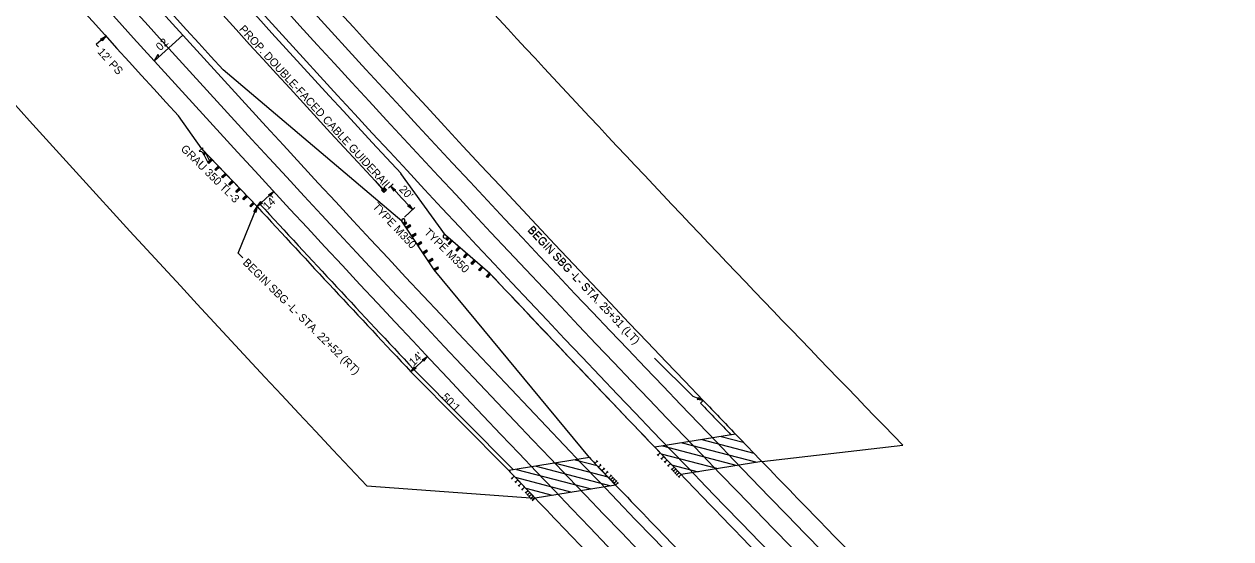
# Model space of a CAD drawing. Extents: x 1602193 to 1605074, y 908180 to 910630.
# Drawn here: x 1602900 to 1603654, y 909219 to 909541 of the extents above; entities that cross this region are included whole.
import ezdxf

# ---------------------------------------------------------------- set-up
doc = ezdxf.new("R2010")
doc.units = 0
for name, color, linetype in [('Prop Approach Slab', 7, 'Continuous'), ('Prop Approach Slab Hatching', 7, 'Continuous'), ('Prop Cable Guiderail Anchor Unit CELL', 7, 'Continuous'), ('Prop Cable Guiderail Double Face', 7, 'Continuous'), ('Prop Conc Shoulder Berm Gutter', 7, 'Continuous'), ('Prop Dimension', 7, 'Continuous'), ('Prop Dimension Text', 7, 'Continuous'), ('Prop DSN Text', 7, 'Continuous'), ('Prop EOT', 7, 'Continuous'), ('Prop Fence Woven Wire', 7, 'Continuous'), ('Prop Guardrail', 7, 'Continuous'), ('Prop Guardrail Anchor Unit CELL', 7, 'Continuous'), ('Prop Lane Lines', 7, 'Continuous'), ('Prop Paved Shoulder', 7, 'Continuous'), ('Prop Roadway Bridge', 7, 'Continuous'), ('Prop Structure Anchor Unit CELL', 7, 'Continuous'), ('Prop Superelevation  Arrow CELL', 7, 'Continuous'), ('Prop Superelevation Label', 7, 'Continuous')]:
    doc.layers.add(name, color=color, linetype=linetype)

msp = doc.modelspace()

# ---------------------------------------------------------------- linework, layer by layer
at = {"layer": 'Prop Approach Slab'}
for p, q in [((1603344.36, 909284.54), (1603293.92, 909276.42)), ((1603253.14, 909269.86), (1603202.83, 909261.76))]:
    msp.add_line(p, q, dxfattribs=at)
for radius, start, end in [(14299.86, 223.910608, 224.005758), (14341.86, 223.794227, 223.888965), (14375.86, 223.700621, 223.795026), (14417.86, 223.585755, 223.679755)]:
    msp.add_arc((1613646.31, 919202), radius, start, end, dxfattribs=at)
at = {"layer": 'Prop Approach Slab Hatching'}
for p, q in [((1603311.07, 909279.18), (1603357.71, 909266.94)), ((1603323.28, 909281.15), (1603355.88, 909272.59)), ((1603335.48, 909283.11), (1603349.21, 909279.51)), ((1603297.87, 909272.31), (1603333.29, 909263.01)), ((1603298.86, 909277.22), (1603345.5, 909264.98)), ((1603207.63, 909262.53), (1603254.28, 909250.29)), ((1603219.84, 909264.5), (1603266.49, 909252.26)), ((1603232.05, 909266.46), (1603264.54, 909257.94)), ((1603244.26, 909268.43), (1603257.94, 909264.84)), ((1603304.5, 909265.4), (1603321.08, 909261.05)), ((1603206.8, 909257.58), (1603242.07, 909248.33)), ((1603213.37, 909250.69), (1603229.86, 909246.36))]:
    msp.add_line(p, q, dxfattribs=at)
at = {"layer": 'Prop Cable Guiderail Anchor Unit CELL'}
for p, q in [((1603108.43, 909454.43), (1603119.29, 909442.68)), ((1603119.29, 909442.68), (1603124.72, 909436.81)), ((1603119.29, 909442.68), (1603124.87, 909436.94)), ((1603119.29, 909442.68), (1603124.56, 909436.68)), ((1603119.29, 909442.68), (1603119.29, 909442.68)), ((1603124.78, 909438.22), (1603123.31, 909436.86)), ((1603124.67, 909435.39), (1603123.31, 909436.86)), ((1603124.86, 909437.27), (1603124.25, 909436.71)), ((1603124.59, 909436.34), (1603124.25, 909436.71)), ((1603125.2, 909436.91), (1603124.59, 909436.34)), ((1603126.14, 909436.75), (1603124.67, 909435.39)), ((1603126.14, 909436.75), (1603124.78, 909438.22)), ((1603125.2, 909436.91), (1603124.86, 909437.27))]:
    msp.add_line(p, q, dxfattribs=at)
at = {"layer": 'Prop Cable Guiderail Double Face'}
msp.add_arc((1613646.31, 919202), 14354.86, 219.580763, 222.768936, dxfattribs=at)
at = {"layer": 'Prop Conc Shoulder Berm Gutter'}
msp.add_line((1603141.65, 909323.51), (1603202.83, 909261.76), dxfattribs=at)
for radius, start, end in [(14419.86, 222.680346, 223.240451), (14299.86, 223.794464, 223.910608)]:
    msp.add_arc((1613646.31, 919202), radius, start, end, dxfattribs=at)
at = {"layer": 'Prop Dimension'}
for p, q in [((1603055.88, 909436.16), (1603045.59, 909426.67)), ((1603130.45, 909440.76), (1603127.6, 909438.11)), ((1603144.1, 909426.16), (1603137.63, 909420.14)), ((1603151.85, 909333.1), (1603141.65, 909323.51))]:
    msp.add_line(p, q, dxfattribs=at)
msp.add_arc((1613646.31, 919202), 14349.94, 222.868721, 222.948526, dxfattribs=at)
at = {"layer": 'Prop Dimension Text'}
for p, q in [((1602951.05, 909533.17), (1602945.12, 909527.8)), ((1602945.12, 909527.8), (1602946.47, 909526.32))]:
    msp.add_line(p, q, dxfattribs=at)
at = {"layer": 'Prop DSN Text'}
for p, q in [((1603033.65, 909397.62), (1603045.59, 909426.67)), ((1603033.65, 909397.62), (1603036.7, 909394.6)), ((1603317.98, 909308), (1603293.74, 909331.98)), ((1603324.28, 909305.45), (1603317.98, 909308))]:
    msp.add_line(p, q, dxfattribs=at)
for points in [[(1602947.79, 909531.11), (1602951.05, 909533.17), (1602948.68, 909530.12), (1602948.58, 909530.93)], [(1603052.63, 909434.07), (1603055.88, 909436.16), (1603053.54, 909433.09), (1603053.43, 909433.9)], [(1603131.12, 909436.2), (1603129.03, 909439.44), (1603132.1, 909437.1), (1603131.3, 909436.99)], [(1603048.83, 909428.76), (1603045.59, 909426.67), (1603047.93, 909429.74), (1603048.04, 909428.93)], [(1603043.52, 909423.41), (1603045.59, 909426.67), (1603044.76, 909422.9), (1603044.32, 909423.58)], [(1603140.53, 909428.03), (1603142.63, 909424.8), (1603139.56, 909427.12), (1603140.36, 909427.24)], [(1603148.62, 909330.98), (1603151.85, 909333.1), (1603149.54, 909330.01), (1603149.42, 909330.81)], [(1603144.88, 909325.63), (1603141.65, 909323.51), (1603143.96, 909326.6), (1603144.08, 909325.79)], [(1603321, 909307.49), (1603324.28, 909305.45), (1603320.5, 909306.25), (1603321.19, 909306.7)]]:
    msp.add_lwpolyline(points, close=True, dxfattribs=at)
at = {"layer": 'Prop EOT'}
for radius, start, end in [(14311.86, 219.480877, 227.661141), (14335.86, 219.480979, 227.66104), (14381.86, 219.480979, 227.66104), (14405.86, 219.479716, 227.662303)]:
    msp.add_arc((1613646.31, 919202), radius, start, end, dxfattribs=at)
at = {"layer": 'Prop Fence Woven Wire'}
for p, q in [((1603360.85, 909267.45), (1603448.88, 909277.66)), ((1603114.19, 909252.19), (1603219.15, 909244.64))]:
    msp.add_line(p, q, dxfattribs=at)
for centre, radius, start, end in [((1613600.64, 919155.95), 14423.95, 219.415042, 223.36309), ((1613597.21, 919158.4), 14163.95, 222.076817, 224.234567)]:
    msp.add_arc(centre, radius, start, end, dxfattribs=at)
at = {"layer": 'Prop Guardrail'}
for p, q in [((1603253.14, 909269.86), (1603156.2, 909387.08)), ((1603141.65, 909323.51), (1603202.83, 909261.76))]:
    msp.add_line(p, q, dxfattribs=at)
for radius, start, end in [(14419.86, 222.680346, 223.240451), (14341.86, 223.196842, 223.814059), (14375.86, 223.700621, 223.720297), (14417.86, 223.585755, 223.605244)]:
    msp.add_arc((1613646.31, 919202), radius, start, end, dxfattribs=at)
at = {"layer": 'Prop Guardrail Anchor Unit CELL'}
for p, q in [((1603011.57, 909463.31), (1603009.42, 909461.32)), ((1603009.42, 909461.32), (1603010.84, 909461.03)), ((1603010.84, 909461.03), (1603012.24, 909459.53)), ((1603011.74, 909461.87), (1603011.57, 909463.31)), ((1603013.13, 909460.36), (1603011.74, 909461.87)), ((1603012.86, 909460.75), (1603011.78, 909459.71)), ((1603011.78, 909459.71), (1603013.55, 909460.03)), ((1603012.47, 909458.99), (1603011.78, 909459.71)), ((1603012.47, 909458.99), (1603012.13, 909459.35)), ((1603012.24, 909459.53), (1603012.68, 909459.95)), ((1603012.86, 909460.75), (1603012.47, 909458.99)), ((1603013.55, 909460.03), (1603012.47, 909458.99)), ((1603014.74, 909454.38), (1603012.47, 909458.99)), ((1603012.68, 909459.95), (1603013.13, 909460.36)), ((1603045.59, 909426.67), (1603013.21, 909460.39)), ((1603015.84, 909455.44), (1603013.55, 909460.03)), ((1603016.95, 909456.5), (1603014.74, 909454.38)), ((1603014.74, 909454.38), (1603016.54, 909454.71)), ((1603015.43, 909453.65), (1603014.74, 909454.38)), ((1603017.64, 909455.78), (1603015.43, 909453.65)), ((1603015.84, 909455.44), (1603015.43, 909453.65)), ((1603017.64, 909455.78), (1603015.84, 909455.44)), ((1603016.54, 909454.71), (1603015.84, 909455.44)), ((1603016.54, 909454.71), (1603016.95, 909456.5)), ((1603021.31, 909451.95), (1603019.15, 909449.87)), ((1603022.01, 909451.23), (1603019.84, 909449.15)), ((1603020.23, 909450.91), (1603019.84, 909449.15)), ((1603022.01, 909451.23), (1603020.23, 909450.91)), ((1603020.92, 909450.19), (1603020.23, 909450.91)), ((1603020.92, 909450.19), (1603021.31, 909451.95)), ((1603019.15, 909449.87), (1603020.92, 909450.19)), ((1603019.84, 909449.15), (1603019.15, 909449.87)), ((1603025.68, 909447.41), (1603023.41, 909445.23)), ((1603023.41, 909445.23), (1603025.24, 909445.6)), ((1603024.11, 909444.51), (1603023.41, 909445.23)), ((1603026.37, 909446.68), (1603024.11, 909444.51)), ((1603024.55, 909446.32), (1603024.11, 909444.51)), ((1603026.37, 909446.68), (1603024.55, 909446.32)), ((1603025.24, 909445.6), (1603024.55, 909446.32)), ((1603025.24, 909445.6), (1603025.68, 909447.41)), ((1603030.04, 909442.86), (1603027.85, 909440.76)), ((1603027.85, 909440.76), (1603029.64, 909441.09)), ((1603028.54, 909440.04), (1603027.85, 909440.76)), ((1603030.73, 909442.14), (1603028.54, 909440.04)), ((1603028.95, 909441.81), (1603028.54, 909440.04)), ((1603030.73, 909442.14), (1603028.95, 909441.81)), ((1603029.64, 909441.09), (1603028.95, 909441.81)), ((1603029.64, 909441.09), (1603030.04, 909442.86)), ((1603030.73, 909442.14), (1603030.04, 909442.86)), ((1603034.4, 909438.31), (1603032.21, 909436.2)), ((1603032.21, 909436.2), (1603034, 909436.54)), ((1603032.9, 909435.48), (1603032.21, 909436.2)), ((1603035.1, 909437.59), (1603032.9, 909435.48)), ((1603033.3, 909437.26), (1603032.9, 909435.48)), ((1603035.1, 909437.59), (1603033.3, 909437.26)), ((1603034, 909436.54), (1603033.3, 909437.26)), ((1603034, 909436.54), (1603034.4, 909438.31)), ((1603038.77, 909433.77), (1603036.57, 909431.66)), ((1603036.57, 909431.66), (1603038.36, 909431.99)), ((1603037.26, 909430.93), (1603036.57, 909431.66)), ((1603039.46, 909433.05), (1603037.26, 909430.93)), ((1603037.67, 909432.71), (1603037.26, 909430.93)), ((1603039.46, 909433.05), (1603037.67, 909432.71)), ((1603038.36, 909431.99), (1603037.67, 909432.71)), ((1603038.36, 909431.99), (1603038.77, 909433.77)), ((1603043.13, 909429.22), (1603040.97, 909427.15)), ((1603043.83, 909428.5), (1603041.66, 909426.43)), ((1603042.05, 909428.18), (1603041.66, 909426.43)), ((1603043.13, 909429.22), (1603042.05, 909428.18)), ((1603042.05, 909428.18), (1603043.83, 909428.5)), ((1603042.74, 909427.46), (1603042.05, 909428.18)), ((1603042.74, 909427.46), (1603043.13, 909429.22)), ((1603043.83, 909428.5), (1603043.13, 909429.22)), ((1603040.97, 909427.15), (1603042.74, 909427.46)), ((1603041.66, 909426.43), (1603040.97, 909427.15)), ((1603137.24, 909415.7), (1603136.03, 909417.52)), ((1603136.86, 909416.28), (1603138.2, 909417.17)), ((1603136.86, 909416.28), (1603137.45, 909416.67)), ((1603136.86, 909416.28), (1603137.45, 909416.67)), ((1603136.86, 909416.28), (1603138.98, 909416)), ((1603137.24, 909415.7), (1603137.93, 909416.15)), ((1603156.2, 909387.08), (1603137.24, 909415.7)), ((1603137.79, 909417.74), (1603137.45, 909416.67)), ((1603137.63, 909415.11), (1603138.2, 909417.17)), ((1603138.98, 909416), (1603137.63, 909415.11)), ((1603138.2, 909417.17), (1603138.98, 909416)), ((1603138.53, 909413.76), (1603140.98, 909415.38)), ((1603140.33, 909413.76), (1603138.53, 909413.76)), ((1603138.8, 909413.34), (1603139.43, 909413.76)), ((1603139.08, 909412.93), (1603139.77, 909414.59)), ((1603139.08, 909412.93), (1603141.53, 909414.55)), ((1603140.33, 909413.76), (1603139.77, 909414.59)), ((1603139.77, 909414.59), (1603141.53, 909414.55)), ((1603140.98, 909415.38), (1603140.33, 909413.76)), ((1603141.53, 909414.55), (1603140.98, 909415.38)), ((1603142.01, 909408.51), (1603144.46, 909410.13)), ((1603143.81, 909408.5), (1603142.01, 909408.51)), ((1603142.56, 909407.68), (1603143.25, 909409.34)), ((1603142.56, 909407.68), (1603145.01, 909409.3)), ((1603143.81, 909408.5), (1603143.25, 909409.34)), ((1603143.25, 909409.34), (1603145.01, 909409.3)), ((1603144.46, 909410.13), (1603143.81, 909408.5)), ((1603145.01, 909409.3), (1603144.46, 909410.13)), ((1603162.89, 909407.01), (1603163.99, 909407.21)), ((1603164.98, 909407.29), (1603163.32, 909408.72)), ((1603164.45, 909407.75), (1603163.4, 909406.53)), ((1603165.51, 909406.84), (1603163.4, 909406.53)), ((1603163.4, 909406.53), (1603164.46, 909405.61)), ((1603164.45, 909407.75), (1603163.99, 909407.21)), ((1603164.45, 909407.75), (1603163.99, 909407.21)), ((1603164.98, 909407.29), (1603164.44, 909406.67)), ((1603164.45, 909407.75), (1603164.46, 909405.61)), ((1603164.46, 909405.61), (1603165.51, 909406.84)), ((1603166.74, 909405.77), (1603164.83, 909403.55)), ((1603191, 909384.9), (1603164.98, 909407.29)), ((1603166.53, 909403.99), (1603166.74, 909405.77)), ((1603145.48, 909403.26), (1603147.93, 909404.88)), ((1603147.29, 909403.25), (1603145.48, 909403.26)), ((1603146.04, 909402.42), (1603146.73, 909404.09)), ((1603146.04, 909402.42), (1603148.49, 909404.05)), ((1603147.29, 909403.25), (1603146.73, 909404.09)), ((1603146.73, 909404.09), (1603148.49, 909404.05)), ((1603147.93, 909404.88), (1603147.29, 909403.25)), ((1603148.49, 909404.05), (1603147.93, 909404.88)), ((1603148.96, 909398), (1603151.41, 909399.63)), ((1603150.76, 909398), (1603148.96, 909398)), ((1603149.51, 909397.17), (1603150.21, 909398.83)), ((1603149.51, 909397.17), (1603151.96, 909398.79)), ((1603150.76, 909398), (1603150.21, 909398.83)), ((1603150.21, 909398.83), (1603151.96, 909398.79)), ((1603151.41, 909399.63), (1603150.76, 909398)), ((1603151.96, 909398.79), (1603151.41, 909399.63)), ((1603164.83, 909403.55), (1603166.53, 909403.99)), ((1603165.59, 909402.89), (1603164.83, 909403.55)), ((1603167.5, 909405.12), (1603165.59, 909402.89)), ((1603165.77, 909404.64), (1603165.59, 909402.89)), ((1603167.5, 909405.12), (1603165.77, 909404.64)), ((1603166.53, 909403.99), (1603165.77, 909404.64)), ((1603167.13, 909405.45), (1603166.64, 909404.88)), ((1603171.52, 909401.66), (1603169.6, 909399.44)), ((1603169.6, 909399.44), (1603171.3, 909399.87)), ((1603170.36, 909398.78), (1603169.6, 909399.44)), ((1603172.28, 909401.01), (1603170.36, 909398.78)), ((1603170.54, 909400.53), (1603170.36, 909398.78)), ((1603172.28, 909401.01), (1603170.54, 909400.53)), ((1603171.3, 909399.87), (1603170.54, 909400.53)), ((1603171.3, 909399.87), (1603171.52, 909401.66)), ((1603152.44, 909392.75), (1603154.89, 909394.37)), ((1603154.24, 909392.75), (1603152.44, 909392.75)), ((1603152.99, 909391.92), (1603153.69, 909393.58)), ((1603152.99, 909391.92), (1603155.44, 909393.54)), ((1603154.24, 909392.75), (1603153.69, 909393.58)), ((1603153.69, 909393.58), (1603155.44, 909393.54)), ((1603154.89, 909394.37), (1603154.24, 909392.75)), ((1603155.44, 909393.54), (1603154.89, 909394.37)), ((1603176.29, 909397.55), (1603174.38, 909395.33)), ((1603174.38, 909395.33), (1603176.07, 909395.76)), ((1603175.14, 909394.67), (1603174.38, 909395.33)), ((1603177.05, 909396.9), (1603175.14, 909394.67)), ((1603175.32, 909396.42), (1603175.14, 909394.67)), ((1603177.05, 909396.9), (1603175.32, 909396.42)), ((1603176.07, 909395.76), (1603175.32, 909396.42)), ((1603176.07, 909395.76), (1603176.29, 909397.55)), ((1603181.07, 909393.44), (1603179.15, 909391.22)), ((1603179.15, 909391.22), (1603180.85, 909391.65)), ((1603179.91, 909390.56), (1603179.15, 909391.22)), ((1603181.83, 909392.79), (1603179.91, 909390.56)), ((1603180.09, 909392.31), (1603179.91, 909390.56)), ((1603181.83, 909392.79), (1603180.09, 909392.31)), ((1603180.85, 909391.65), (1603180.09, 909392.31)), ((1603180.85, 909391.65), (1603181.07, 909393.44)), ((1603155.92, 909387.5), (1603158.37, 909389.12)), ((1603157.72, 909387.49), (1603155.92, 909387.5)), ((1603156.47, 909386.67), (1603157.17, 909388.33)), ((1603156.47, 909386.67), (1603158.92, 909388.29)), ((1603157.72, 909387.49), (1603157.17, 909388.33)), ((1603157.17, 909388.33), (1603158.92, 909388.29)), ((1603158.37, 909389.12), (1603157.72, 909387.49)), ((1603158.92, 909388.29), (1603158.37, 909389.12)), ((1603185.84, 909389.33), (1603183.93, 909387.11)), ((1603183.93, 909387.11), (1603185.62, 909387.54)), ((1603184.69, 909386.46), (1603183.93, 909387.11)), ((1603186.6, 909388.68), (1603184.69, 909386.46)), ((1603184.87, 909388.2), (1603184.69, 909386.46)), ((1603186.6, 909388.68), (1603184.87, 909388.2)), ((1603185.62, 909387.54), (1603184.87, 909388.2)), ((1603185.62, 909387.54), (1603185.84, 909389.33)), ((1603190.62, 909385.22), (1603188.7, 909383)), ((1603188.7, 909383), (1603190.4, 909383.43)), ((1603189.46, 909382.35), (1603188.7, 909383)), ((1603191.38, 909384.57), (1603189.46, 909382.35)), ((1603189.64, 909384.09), (1603189.46, 909382.35)), ((1603191.38, 909384.57), (1603189.64, 909384.09)), ((1603190.4, 909383.43), (1603189.64, 909384.09)), ((1603190.4, 909383.43), (1603190.62, 909385.22))]:
    msp.add_line(p, q, dxfattribs=at)
for centre, major_axis, start_param, end_param in [((1603136.86, 909418.07), (-0.828, -0.548), 2.210226, 6.283185), ((1603162.67, 909407.97), (-0.648, -0.753), 3.141593, 7.214552)]:
    msp.add_ellipse(centre, major_axis=major_axis, ratio=0.995379, start_param=start_param, end_param=end_param, dxfattribs=at)
at = {"layer": 'Prop Lane Lines'}
for radius in [14323.86, 14393.86]:
    msp.add_arc((1613646.31, 919202), radius, 219.480979, 227.66104, dxfattribs=at)
at = {"layer": 'Prop Paved Shoulder'}
for p, q in [((1603136.03, 909417.52), (1603024.34, 909511.97)), ((1603010.95, 909462.74), (1602996.38, 909483.27)), ((1603045.59, 909426.67), (1603010.95, 909462.74)), ((1603163.32, 909408.72), (1603135.44, 909447.34)), ((1603047.3, 909428.25), (1603045.59, 909426.67)), ((1603156.2, 909387.08), (1603136.03, 909417.52)), ((1603191, 909384.9), (1603163.32, 909408.72)), ((1603253.14, 909269.86), (1603156.2, 909387.08)), ((1603143.31, 909325.15), (1603205.66, 909262.21)), ((1603324.28, 909305.45), (1603322.6, 909303.83))]:
    msp.add_line(p, q, dxfattribs=at)
for radius, start, end in [(14299.86, 219.480979, 223.794464), (14339.86, 219.480979, 222.863015), (14377.86, 219.48119, 222.373049), (14417.86, 219.480979, 222.382421), (14417.53, 222.680346, 223.240451), (14341.86, 223.196842, 223.794227), (14302.19, 223.794464, 223.90412)]:
    msp.add_arc((1613646.31, 919202), radius, start, end, dxfattribs=at)
at = {"layer": 'Prop Roadway Bridge'}
for p, q in [((1603360.85, 909267.45), (1603310.35, 909259.32)), ((1603269.52, 909252.75), (1603219.15, 909244.64))]:
    msp.add_line(p, q, dxfattribs=at)
for radius, start, end in [(14299.86, 224.005758, 224.459436), (14341.86, 223.888965, 224.340663), (14375.86, 223.795026, 224.245138), (14417.86, 223.679755, 224.127924)]:
    msp.add_arc((1613646.31, 919202), radius, start, end, dxfattribs=at)
at = {"layer": 'Prop Structure Anchor Unit CELL'}
for p, q in [((1603296.31, 909271.04), (1603295.52, 909271.87)), ((1603297.36, 909272.84), (1603295.92, 909271.45)), ((1603310.35, 909259.32), (1603297.36, 909272.84)), ((1603299.52, 909270.59), (1603298.08, 909269.2)), ((1603256.55, 909266.29), (1603257.99, 909267.67)), ((1603269.52, 909252.75), (1603256.55, 909266.29)), ((1603258.39, 909267.26), (1603257.6, 909268.09)), ((1603258.71, 909264.03), (1603260.16, 909265.42)), ((1603260.55, 909265), (1603259.76, 909265.83)), ((1603260.87, 909261.78), (1603262.32, 909263.16)), ((1603262.71, 909262.75), (1603261.92, 909263.57)), ((1603298.48, 909268.79), (1603297.68, 909269.61)), ((1603300.64, 909266.53), (1603299.85, 909267.36)), ((1603301.69, 909268.33), (1603300.25, 909266.95)), ((1603302.81, 909264.28), (1603302.01, 909265.11)), ((1603303.85, 909266.08), (1603302.41, 909264.69)), ((1603304.97, 909262.03), (1603304.18, 909262.85)), ((1603306.02, 909263.83), (1603304.58, 909262.44)), ((1603307.1, 909262.7), (1603305.66, 909261.31)), ((1603205.16, 909256.41), (1603204.36, 909257.24)), ((1603206.21, 909258.21), (1603204.76, 909256.83)), ((1603219.15, 909244.64), (1603206.21, 909258.21)), ((1603207.31, 909254.15), (1603206.52, 909254.98)), ((1603208.36, 909255.95), (1603206.92, 909254.56)), ((1603263.03, 909259.52), (1603264.48, 909260.9)), ((1603264.87, 909260.49), (1603264.08, 909261.32)), ((1603265.2, 909257.26), (1603266.64, 909258.65)), ((1603267.04, 909258.23), (1603266.24, 909259.06)), ((1603266.28, 909256.13), (1603267.72, 909257.52)), ((1603268.12, 909257.1), (1603267.32, 909257.93)), ((1603267.36, 909255), (1603268.8, 909256.39)), ((1603269.2, 909255.97), (1603268.41, 909256.8)), ((1603268.44, 909253.88), (1603269.88, 909255.26)), ((1603270.28, 909254.85), (1603269.49, 909255.67)), ((1603306.05, 909260.9), (1603305.26, 909261.73)), ((1603307.14, 909259.77), (1603306.34, 909260.6)), ((1603308.18, 909261.57), (1603306.74, 909260.19)), ((1603308.22, 909258.65), (1603307.43, 909259.47)), ((1603309.26, 909260.45), (1603307.82, 909259.06)), ((1603309.3, 909257.52), (1603308.51, 909258.35)), ((1603310.35, 909259.32), (1603308.91, 909257.93)), ((1603209.47, 909251.89), (1603208.68, 909252.72)), ((1603210.52, 909253.68), (1603209.07, 909252.3)), ((1603211.63, 909249.63), (1603210.83, 909250.46)), ((1603212.68, 909251.42), (1603211.23, 909250.04)), ((1603213.78, 909247.37), (1603212.99, 909248.2)), ((1603214.83, 909249.16), (1603213.39, 909247.78)), ((1603215.91, 909248.03), (1603214.47, 909246.65)), ((1603269.52, 909252.75), (1603270.96, 909254.13)), ((1603271.36, 909253.72), (1603270.57, 909254.54)), ((1603214.86, 909246.24), (1603214.07, 909247.06)), ((1603215.94, 909245.1), (1603215.15, 909245.93)), ((1603216.99, 909246.9), (1603215.54, 909245.52)), ((1603217.02, 909243.97), (1603216.23, 909244.8)), ((1603218.07, 909245.77), (1603216.62, 909244.39)), ((1603218.1, 909242.84), (1603217.31, 909243.67)), ((1603219.15, 909244.64), (1603217.7, 909243.26))]:
    msp.add_line(p, q, dxfattribs=at)
at = {"layer": 'Prop Superelevation  Arrow CELL'}
msp.add_line((1602999.14, 909533.71), (1602981.37, 909517.58), dxfattribs=at)
msp.add_lwpolyline([(1602981.37, 909517.58), (1602983.7, 909521.71), (1602983.94, 909519.91)], close=True, dxfattribs=at)

# ---------------------------------------------------------------- texts
at = {"layer": 'Prop Cable Guiderail Double Face'}
msp.add_text('PROP. DOUBLE-FACED CABLE GUIDERAIL', height=5, rotation=312.64295, dxfattribs=at).set_placement((1603034.01, 909537.15))
at = {"layer": 'Prop Dimension'}
for s, rotation, p in [("20'", 312.90858, (1603133.92, 909437.1)), ("14'", 42.68035, (1603051.96, 909424.19)), ("14'", 43.24045, (1603143.27, 909326.75)), ('50:1', 314.73156, (1603160.41, 909307.24))]:
    msp.add_text(s, height=5, rotation=rotation, dxfattribs=at).set_placement(p)
at = {"layer": 'Prop Dimension Text'}
msp.add_text("12' PS", height=5, rotation=312.15427, dxfattribs=at).set_placement((1602945.52, 909522.99))
at = {"layer": 'Prop DSN Text'}
for s, rotation, p in [('BEGIN SBG -L- STA. 25+31 (LT)', 313.43996, (1603214.03, 909411.59)), ('BEGIN SBG -L- STA. 25+31 (LT)', 313.2269, (1603214.28, 909411.85)), ('BEGIN SBG -L- STA. 22+52 (RT)', 315.29764, (1603036.21, 909391.21))]:
    msp.add_text(s, height=5, rotation=rotation, dxfattribs=at).set_placement(p)
at = {"layer": 'Prop Guardrail Anchor Unit CELL'}
for s, rotation, p in [('GRAU 350 TL-3', 315.29764, (1602997.48, 909462.26)), ('TYPE M350', 313.11322, (1603117.32, 909426.23)), ('TYPE M350', 315.29764, (1603149.53, 909410.12))]:
    msp.add_text(s, height=5, rotation=rotation, dxfattribs=at).set_placement(p)
at = {"layer": 'Prop Superelevation Label'}
msp.add_text('02', height=5, rotation=42.24141, dxfattribs=at).set_placement((1602985.07, 909523.64))

doc.saveas('drawing.dxf')
